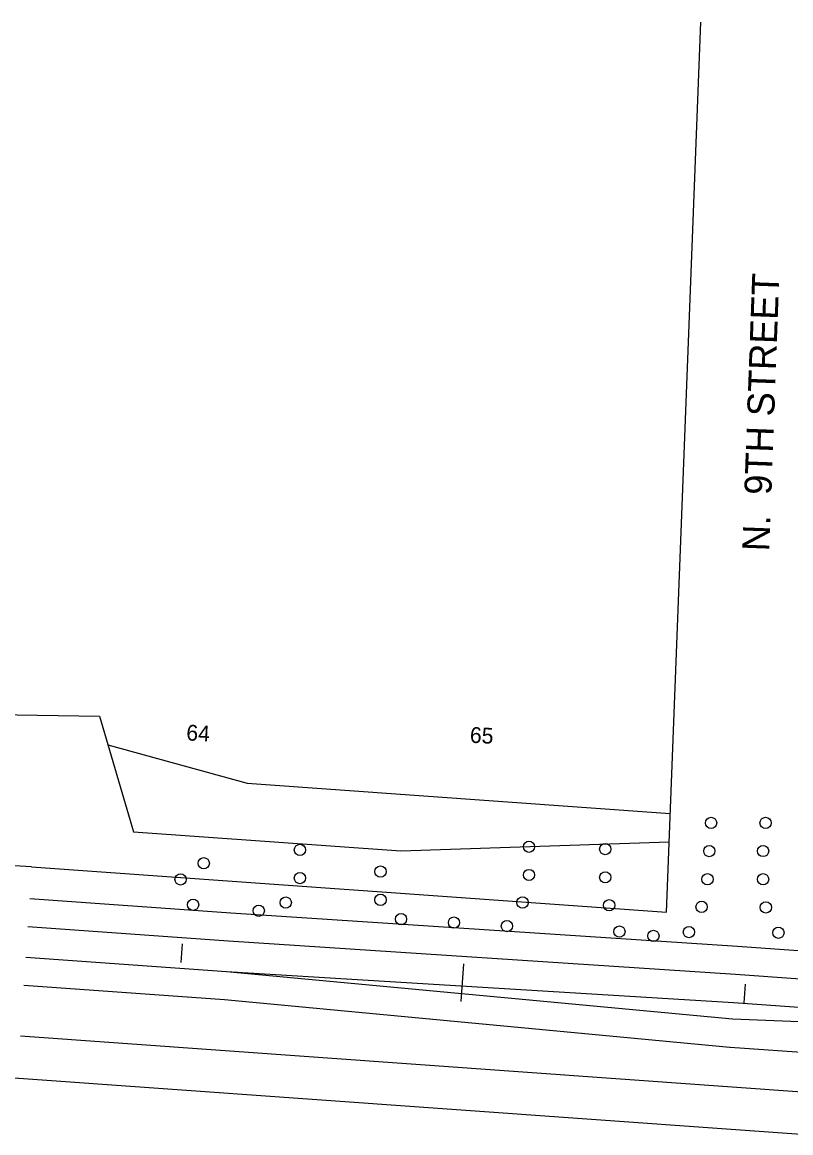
# Model space of a CAD drawing. Extents: x 0 to 1361828, y 0 to 1470398.
# Drawn here: x 685616.5 to 685888.8, y 734825.2 to 735218.4 of the extents above; entities that cross this region are included whole.
import ezdxf

# ---------------------------------------------------------------- set-up
doc = ezdxf.new("R2010")
doc.units = 0
for name, color, linetype in [('$', 7, 'Continuous'), ('BASE', 7, 'Continuous'), ('MOT Stage 1', 7, 'Continuous'), ('MOT Stage 1 Lanes', 7, 'Continuous'), ('R_Horz Alg Station', 7, 'Continuous'), ('RW-EX', 7, 'Continuous'), ('RW-PR', 7, 'Continuous')]:
    doc.layers.add(name, color=color, linetype=linetype)

# ---------------------------------------------------------------- blocks, each defined once
blk = doc.blocks.new('BAREL_1776')
at = {"layer": 'MOT Stage 1'}
blk.add_circle((0, 0.01), 2.88, dxfattribs=at)
blk = doc.blocks.new('BAREL_1777')
at = {"layer": 'MOT Stage 1'}
blk.add_circle((0, 0.01), 2.88, dxfattribs=at)
blk = doc.blocks.new('BAREL_1778')
at = {"layer": 'MOT Stage 1'}
blk.add_circle((0, 0.01), 2.88, dxfattribs=at)
blk = doc.blocks.new('BAREL_1779')
at = {"layer": 'MOT Stage 1'}
blk.add_circle((0, 0.01), 2.88, dxfattribs=at)
blk = doc.blocks.new('BAREL_1790')
at = {"layer": 'MOT Stage 1'}
blk.add_circle((0, 0.01), 2.88, dxfattribs=at)
blk = doc.blocks.new('BAREL_1791')
at = {"layer": 'MOT Stage 1'}
blk.add_circle((0, 0.01), 2.88, dxfattribs=at)
blk = doc.blocks.new('BAREL_1792')
at = {"layer": 'MOT Stage 1'}
blk.add_circle((0, 0.01), 2.88, dxfattribs=at)
blk = doc.blocks.new('BAREL_1793')
at = {"layer": 'MOT Stage 1'}
blk.add_circle((0, 0.01), 2.88, dxfattribs=at)
blk = doc.blocks.new('BAREL_1794')
at = {"layer": 'MOT Stage 1'}
blk.add_circle((0, 0.01), 2.88, dxfattribs=at)
blk = doc.blocks.new('BAREL_1795')
at = {"layer": 'MOT Stage 1'}
blk.add_circle((0, 0.01), 2.88, dxfattribs=at)
blk = doc.blocks.new('BAREL_1811')
at = {"layer": 'MOT Stage 1'}
blk.add_circle((0, 0.01), 2.88, dxfattribs=at)
blk = doc.blocks.new('BAREL_1812')
at = {"layer": 'MOT Stage 1'}
blk.add_circle((0, 0.01), 2.88, dxfattribs=at)
blk = doc.blocks.new('BAREL_1813')
at = {"layer": 'MOT Stage 1'}
blk.add_circle((0, 0.01), 2.88, dxfattribs=at)
blk = doc.blocks.new('BAREL_1814')
at = {"layer": 'MOT Stage 1'}
blk.add_circle((0, 0.01), 2.88, dxfattribs=at)
blk = doc.blocks.new('BAREL_1815')
at = {"layer": 'MOT Stage 1'}
blk.add_circle((0, 0.01), 2.88, dxfattribs=at)
blk = doc.blocks.new('BAREL_1816')
at = {"layer": 'MOT Stage 1'}
blk.add_circle((0, 0.01), 2.88, dxfattribs=at)
blk = doc.blocks.new('BAREL_1817')
at = {"layer": 'MOT Stage 1'}
blk.add_circle((0, 0.01), 2.88, dxfattribs=at)
blk = doc.blocks.new('BAREL_1818')
at = {"layer": 'MOT Stage 1'}
blk.add_circle((0, 0.01), 2.88, dxfattribs=at)
blk = doc.blocks.new('BAREL_1900')
at = {"layer": 'MOT Stage 1'}
blk.add_circle((0, 0.01), 2.88, dxfattribs=at)
blk = doc.blocks.new('BAREL_1901')
at = {"layer": 'MOT Stage 1'}
blk.add_circle((0, 0.01), 2.88, dxfattribs=at)
blk = doc.blocks.new('BAREL_1902')
at = {"layer": 'MOT Stage 1'}
blk.add_circle((0, 0.01), 2.88, dxfattribs=at)
blk = doc.blocks.new('BAREL_1903')
at = {"layer": 'MOT Stage 1'}
blk.add_circle((0, 0.01), 2.88, dxfattribs=at)
blk = doc.blocks.new('BAREL_1904')
at = {"layer": 'MOT Stage 1'}
blk.add_circle((0, 0.01), 2.88, dxfattribs=at)
blk = doc.blocks.new('BAREL_1905')
at = {"layer": 'MOT Stage 1'}
blk.add_circle((0, 0.01), 2.88, dxfattribs=at)
blk = doc.blocks.new('BAREL_1906')
at = {"layer": 'MOT Stage 1'}
blk.add_circle((0, 0.01), 2.88, dxfattribs=at)
blk = doc.blocks.new('BAREL_1907')
at = {"layer": 'MOT Stage 1'}
blk.add_circle((0, 0.01), 2.88, dxfattribs=at)
blk = doc.blocks.new('BAREL_1908')
at = {"layer": 'MOT Stage 1'}
blk.add_circle((0, 0.01), 2.88, dxfattribs=at)
blk = doc.blocks.new('BAREL_1909')
at = {"layer": 'MOT Stage 1'}
blk.add_circle((0, 0.01), 2.88, dxfattribs=at)
blk = doc.blocks.new('BAREL_1910')
at = {"layer": 'MOT Stage 1'}
blk.add_circle((0, 0.01), 2.88, dxfattribs=at)
blk = doc.blocks.new('BAREL_1915')
at = {"layer": 'MOT Stage 1'}
blk.add_circle((0, 0.01), 2.88, dxfattribs=at)

msp = doc.modelspace()

# ---------------------------------------------------------------- linework, layer by layer
at = {"layer": 'MOT Stage 1 Lanes'}
for p, q in [((685619.21, 734908.22), (685690.35, 734903.13)), ((685690.35, 734903.13), (685869.96, 734891.29)), ((685618.5, 734898.24), (685689.63, 734893.16)), ((685689.63, 734893.16), (685869.25, 734881.32)), ((685617.72, 734887.42), (685688.86, 734882.34)), ((685688.86, 734882.34), (685868.12, 734865.51)), ((685688.86, 734882.34), (685868.53, 734871.34)), ((685617.01, 734877.45), (685688.15, 734872.36)), ((685688.15, 734872.36), (685867.18, 734855.56)), ((685868.12, 734865.51), (686042.67, 734858.89)), ((685867.4, 734855.54), (685951.66, 734849.51))]:
    msp.add_line(p, q, dxfattribs=at)
for points in [[(685869.96, 734891.29), (686151.25, 734871.18)], [(685869.25, 734881.32), (686150.53, 734861.21)], [(685868.53, 734871.34), (686150.82, 734851.16)]]:
    msp.add_lwpolyline(points, dxfattribs=at)
at = {"layer": 'R_Horz Alg Station'}
for points in [[(685673.16, 734892.15), (685672.68, 734885.5)], [(685772.9, 734885.02), (685771.95, 734871.72)], [(685872.65, 734877.89), (685872.17, 734871.24)]]:
    msp.add_lwpolyline(points, dxfattribs=at)
at = {"layer": 'RW-EX'}
for p, q in [((685844.75, 734903.27), (685856.91, 735218.44)), ((685619.8, 734919.36), (685420.64, 734930.82)), ((685619.8, 734919.36), (685844.75, 734903.27)), ((685615.93, 734859.48), (686148.06, 734821.44))]:
    msp.add_line(p, q, dxfattribs=at)
at = {"layer": 'RW-PR'}
for p, q in [((685646.86, 734962.54), (685696.18, 734948.99)), ((685696.18, 734948.99), (685846.1, 734938.27))]:
    msp.add_line(p, q, dxfattribs=at)
for points in [[(685590.46, 734936.07), (685592.61, 734973.51), (685643.83, 734972.78), (685655.94, 734931.81)], [(685655.94, 734931.81), (685750.7, 734925.04), (685845.72, 734928.27)], [(685416.49, 734855.93), (685615.28, 734844.49), (685918.84, 734822.79), (685992.93, 734807.46), (686092.68, 734800.33), (686145.51, 734791.54), (686191.41, 734759.48), (686200.21, 734731.89), (686188.38, 734460.16), (686189.54, 734372.01), (686196.02, 734332.97)]]:
    msp.add_lwpolyline(points, dxfattribs=at)

# ---------------------------------------------------------------- block references
at = {"layer": 'MOT Stage 1', "xscale": 0.6945420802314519, "yscale": 0.6945420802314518, "rotation": 87.04179557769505}
for name, p in [('BAREL_1790', (685860.58, 734934.94)), ('BAREL_1793', (685879.92, 734934.94)), ('BAREL_1903', (685714.89, 734925.38)), ('BAREL_1776', (685796.07, 734926.49)), ('BAREL_1777', (685823.09, 734925.66)), ('BAREL_1791', (685859.97, 734924.96)), ('BAREL_1794', (685879.03, 734924.98)), ('BAREL_1909', (685680.82, 734920.64)), ('BAREL_1902', (685743.45, 734917.7)), ('BAREL_1778', (685796.07, 734916.49)), ('BAREL_1908', (685672.6, 734914.94)), ('BAREL_1904', (685714.89, 734915.38)), ('BAREL_1779', (685823.09, 734915.66)), ('BAREL_1792', (685859.32, 734914.98)), ('BAREL_1795', (685879.03, 734914.98)), ('BAREL_1907', (685677.03, 734905.97)), ('BAREL_1905', (685709.87, 734906.73)), ('BAREL_1901', (685743.45, 734907.7)), ('BAREL_1811', (685793.78, 734906.75)), ('BAREL_1813', (685824.49, 734905.76)), ('BAREL_1815', (685857.25, 734905.2)), ('BAREL_1817', (685880, 734905.03)), ('BAREL_1906', (685700.29, 734903.84)), ('BAREL_1900', (685750.72, 734900.84)), ('BAREL_1915', (685769.49, 734899.63)), ('BAREL_1812', (685788.26, 734898.42)), ('BAREL_1814', (685828.12, 734896.44)), ('BAREL_1910', (685840.16, 734894.9)), ('BAREL_1816', (685852.76, 734896.26)), ('BAREL_1818', (685884.44, 734896.06))]:
    msp.add_blockref(name, p, dxfattribs=at)

# ---------------------------------------------------------------- texts
at = {"layer": '$'}
for s, p in [('64', (685674.53, 734964.16)), ('65', (685775.02, 734963.34))]:
    msp.add_text(s, height=5.6, rotation=357.0415, dxfattribs=at).set_placement(p)
at = {"layer": 'BASE'}
msp.add_text('N.  9TH STREET', height=9.6, rotation=87.9099, dxfattribs=at).set_placement((685881.2, 735030.99))

doc.saveas('drawing.dxf')
